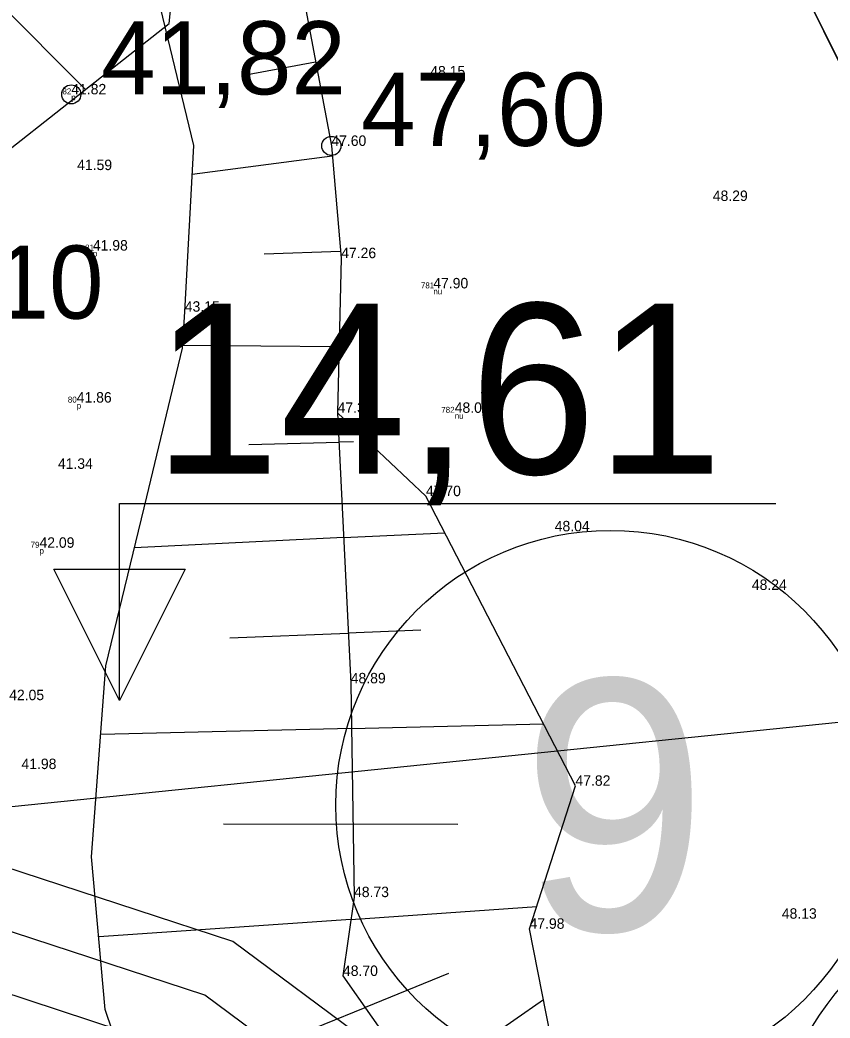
# Model space of a CAD drawing. Extents: x 700746 to 706058, y 6570320 to 6580460.
# Drawn here: x 703085.54 to 703112.68, y 6577214.62 to 6577248.05 of the extents above; entities that cross this region are included whole.
import ezdxf

# ---------------------------------------------------------------- set-up
doc = ezdxf.new("R2010")
doc.units = 0
for name, color, linetype in [('illumineerimisjooned', 7, 'Continuous'), ('jääkpaksus', 7, 'Continuous'), ('Kaevandatud ala', 7, 'Continuous'), ('kataster', 7, 'Continuous'), ('KORGUS-EH2000', 7, 'Continuous'), ('Lõige', 7, 'Continuous'), ('MOOTKOOD', 7, 'Continuous'), ('MOOTKORG-EH2000', 7, 'Continuous'), ('MOOTNR', 7, 'Continuous'), ('PIIR', 7, 'Continuous'), ('Plokid', 7, 'Continuous'), ('RELJEEF', 7, 'Continuous'), ('vahekiht', 7, 'Continuous'), ('VEEKOGU', 7, 'Continuous')]:
    doc.layers.add(name, color=color, linetype=linetype)

msp = doc.modelspace()

# ---------------------------------------------------------------- linework, layer by layer
at = {"layer": 'illumineerimisjooned'}
for points in [[(702862.311, 6577373.596), (702850.89, 6577377.293), (702839.79, 6577379.563), (702831.646, 6577378.473), (702820.821, 6577374.823), (702754.92, 6577346.017), (702742.145, 6577342.939), (702732.615, 6577342.189), (702714.765, 6577344.588), (702715.658, 6577336.409), (703090.802, 6577213.589), (703232.719, 6577108.158), (703252.344, 6577093.719)], [(703167.053, 6577159.433), (703091.733, 6577215.389), (702863.784, 6577290.018)]]:
    msp.add_lwpolyline(points, dxfattribs=at)
at = {"layer": 'jääkpaksus'}
msp.add_lwpolyline([(703088.869, 6577225.258), (703088.869, 6577231.858), (703110.869, 6577231.858)], dxfattribs=at)
msp.add_lwpolyline([(703088.869, 6577225.258), (703086.669, 6577229.658), (703091.069, 6577229.658)], close=True, dxfattribs=at)
at = {"layer": 'Kaevandatud ala'}
msp.add_line((702970.035, 6577363.415), (703087.727, 6577245.723), dxfattribs=at)
msp.add_lwpolyline([(703020.132, 6577213.175), (703028.583, 6577215.712), (703035.429, 6577216.388), (703043.119, 6577223.576), (703046.922, 6577230.341), (703054.529, 6577231.018), (703061.374, 6577228.396), (703067.29, 6577232.033), (703074.812, 6577238.628), (703081.403, 6577240.743), (703090.531, 6577247.93), (703091.499, 6577257.213)], dxfattribs=at)
at = {"layer": 'kataster'}
msp.add_lwpolyline([(702859.8, 6577465.72), (703125.43, 6577441.71), (703167.04, 6577172.32), (703141.54, 6577201.64), (703129.16, 6577218.59), (703119.31, 6577233.95), (703096.08, 6577280.59), (703057.1, 6577329.85), (703041.25, 6577339.7), (703019.19, 6577342.06), (703005.04, 6577344.66), (702961.68, 6577364.05), (702944.77, 6577367.92), (702900.72, 6577367.74), (702878.06, 6577370.59), (702863.2, 6577375.41), (702862.38, 6577440.12)], close=True, dxfattribs=at)
msp.add_lwpolyline([(702754.28, 6577347.92), (702820.1, 6577376.69), (702831.19, 6577380.43), (702839.86, 6577381.59), (702851.4, 6577379.23), (702863.2, 6577375.41), (702878.06, 6577370.59), (702900.72, 6577367.74), (702944.77, 6577367.92), (702961.68, 6577364.05), (703005.04, 6577344.66), (703019.19, 6577342.06), (703041.25, 6577339.7), (703057.1, 6577329.85), (703096.08, 6577280.59), (703119.31, 6577233.95), (703129.16, 6577218.59), (703141.54, 6577201.64), (703167.04, 6577172.32), (703168.73, 6577170.37), (703277.36, 6577072.83), (703231.53, 6577106.55), (703089.87, 6577211.79), (702713.81, 6577334.91)], dxfattribs=at)
at = {"layer": 'KORGUS-EH2000'}
for centre in [(703087.256, 6577245.556), (703095.97, 6577243.83)]:
    msp.add_circle(centre, 0.32, dxfattribs=at)
at = {"layer": 'Lõige'}
msp.add_lwpolyline([(702840.34, 6577295.661), (702901.645, 6577283.339), (702991.177, 6577252.569), (703074.081, 6577220.567), (703131.906, 6577226.463), (703178.085, 6577224.803)], dxfattribs=at)
at = {"layer": 'PIIR'}
for centre in [(703105.32, 6577221.752), (703119.956, 6577209.575)]:
    msp.add_circle(centre, 9.2, dxfattribs=at)
at = {"layer": 'Plokid'}
msp.add_lwpolyline([(703043.339, 6577445.098), (703121.898, 6577438.001), (703148.899, 6577263.565), (703163.227, 6577170.805), (703163.267, 6577170.746), (703164.325, 6577163.951), (703092.665, 6577217.188), (702865.809, 6577291.46), (702867.214, 6577375.329), (702866.384, 6577440.28), (702866.378, 6577440.34), (702866.377, 6577440.346), (702864.268, 6577461.276), (703043.339, 6577445.098)], dxfattribs=at)
at = {"layer": 'RELJEEF'}
for p, q in [((703093.164, 6577246.226), (703095.444, 6577246.64)), ((703096, 6577243.49), (703091.308, 6577242.872)), ((703093.717, 6577240.21), (703096.28, 6577240.303)), ((703096.231, 6577237.104), (703090.988, 6577237.147)), ((703093.209, 6577233.834), (703096.228, 6577233.906)), ((703096.714, 6577233.918), (703096.228, 6577233.906)), ((703096.383, 6577230.71), (703099.773, 6577230.874)), ((703096.383, 6577230.71), (703089.372, 6577230.369)), ((703092.572, 6577227.352), (703096.538, 6577227.514)), ((703098.972, 6577227.613), (703096.538, 6577227.514)), ((703096.643, 6577224.316), (703088.245, 6577224.113)), ((703096.643, 6577224.316), (703103.08, 6577224.471)), ((703092.356, 6577221.128), (703096.692, 6577221.116)), ((703100.212, 6577221.106), (703096.692, 6577221.116)), ((703096.625, 6577217.924), (703102.85, 6577218.355)), ((703096.625, 6577217.924), (703088.174, 6577217.338)), ((703099.891, 6577216.108), (703097.099, 6577214.976)), ((703098.937, 6577212.356), (703103.074, 6577215.247)), ((703093.261, 6577213.418), (703097.099, 6577214.976))]:
    msp.add_line(p, q, dxfattribs=at)
for points in [[(703092.61, 6577254.33), (703094.64, 6577250.94), (703095.97, 6577243.83), (703096.3, 6577240.07), (703096.18, 6577234.89), (703096.62, 6577225.83), (703096.73, 6577218.67), (703096.36, 6577216.03), (703099.27, 6577211.88), (703102.33, 6577207.48), (703108.69, 6577203.21), (703117.07, 6577197.4), (703119.26, 6577195.79), (703122.66, 6577191.02), (703124.13, 6577187.15), (703124.86, 6577183.98), (703126.36, 6577179.97), (703126.31, 6577178.16), (703125.42, 6577175.86), (703122.58, 6577172.87), (703122.53, 6577170.35), (703118.29, 6577167.65), (703112.56, 6577164.26)], [(703094.64, 6577250.94), (703095.97, 6577243.83), (703096.3, 6577240.07), (703096.18, 6577234.89), (703096.62, 6577225.83), (703096.73, 6577218.67), (703096.36, 6577216.03), (703099.27, 6577211.88)], [(703126.58, 6577194.82), (703126.07, 6577196.68), (703123.17, 6577199.85), (703119.24, 6577202.77), (703113.38, 6577206.06), (703109.84, 6577209.12), (703105.94, 6577210.1), (703103.88, 6577211.14), (703102.61, 6577217.61), (703104.15, 6577222.4), (703099.14, 6577232.1), (703096.18, 6577234.89)]]:
    msp.add_lwpolyline(points, dxfattribs=at)
at = {"layer": 'vahekiht'}
msp.add_open_spline([(702979.832, 6577405.847), (702968.107, 6577383.619), (702956.937, 6577340.299), (703007.686, 6577297.989), (703005.438, 6577248.778), (703018.696, 6577224.523), (703025.875, 6577210.26), (703039.06, 6577207.602), (703055.215, 6577200.514), (703065.918, 6577180.529), (703097.43, 6577186.962), (703125.436, 6577225.369), (703148.077, 6577281.443), (703138.931, 6577341.457), (703139.445, 6577382.673), (703130.544, 6577416.204), (703100.319, 6577426.617), (703061.125, 6577412.698), (703017.391, 6577461.228), (702989.678, 6577424.511), (702979.832, 6577405.847)], degree=3, dxfattribs=at)
msp.add_open_spline([(702979.832, 6577405.847), (702968.107, 6577383.619), (702956.937, 6577340.299), (703007.686, 6577297.989), (703005.438, 6577248.778), (703018.696, 6577224.523), (703025.875, 6577210.26), (703039.06, 6577207.602), (703055.215, 6577200.514), (703065.918, 6577180.529), (703097.43, 6577186.962), (703125.436, 6577225.369), (703148.077, 6577281.443), (703138.931, 6577341.457), (703139.445, 6577382.673), (703130.544, 6577416.204), (703100.319, 6577426.617), (703061.125, 6577412.698), (703017.391, 6577461.228), (702989.678, 6577424.511), (702979.832, 6577405.847)], degree=3, dxfattribs=at)
at = {"layer": 'VEEKOGU'}
msp.add_lwpolyline([(703120.39, 6577146.08), (703115.365, 6577147.77), (703110.383, 6577151.071), (703104.69, 6577159.71), (703106.266, 6577165.481), (703105.388, 6577174.722), (703104.887, 6577179.996), (703103.186, 6577185.693), (703099.755, 6577192.609), (703093.54, 6577202.31), (703089.925, 6577210.383), (703088.39, 6577214.903), (703087.936, 6577220.02), (703088.419, 6577226.416), (703089.783, 6577232.073), (703090.983, 6577237.053), (703091.059, 6577238.277), (703091.362, 6577243.838), (703090.24, 6577248.46), (703088.7, 6577253.3)], dxfattribs=at)
msp.add_lwpolyline([(703120.39, 6577146.08), (703115.365, 6577147.77), (703110.383, 6577151.071), (703104.69, 6577159.71), (703106.266, 6577165.481), (703105.388, 6577174.722), (703104.887, 6577179.996), (703103.186, 6577185.693), (703099.755, 6577192.609), (703093.54, 6577202.31), (703089.925, 6577210.383), (703088.39, 6577214.903), (703087.936, 6577220.02), (703088.419, 6577226.416), (703089.783, 6577232.073), (703090.983, 6577237.053), (703091.059, 6577238.277), (703091.362, 6577243.838), (703090.24, 6577248.46), (703088.7, 6577253.3)], dxfattribs=at)

# ---------------------------------------------------------------- texts
at = {"layer": 'jääkpaksus'}
msp.add_text('14,61', height=5.7, rotation=360, dxfattribs=at).set_placement((703090.007, 6577232.847))
at = {"layer": 'KORGUS-EH2000'}
for s, p in [('41,82', (703088.256, 6577245.556)), ('47,60', (703096.97, 6577243.83)), ('38,10', (703080.136, 6577238.043))]:
    msp.add_text(s, height=2.45, dxfattribs=at).set_placement(p)
at = {"layer": 'MOOTKOOD'}
for s, p in [('p', (703087.256, 6577245.356)), ('p', (703087.979, 6577240.125)), ('nu', (703099.386, 6577238.858)), ('p', (703087.439, 6577235.033)), ('nu', (703100.104, 6577234.69)), ('p', (703086.191, 6577230.171))]:
    msp.add_text(s, height=0.2, dxfattribs=at).set_placement(p)
at = {"layer": 'MOOTKORG-EH2000'}
for s, p in [('48.15', (703099.284, 6577246.156)), ('41.82', (703087.256, 6577245.556)), ('47.60', (703095.97, 6577243.83)), ('41.59', (703087.453, 6577243.02)), ('48.29', (703108.752, 6577241.985)), ('41.98', (703087.979, 6577240.325)), ('47.26', (703096.3, 6577240.07)), ('47.90', (703099.386, 6577239.058)), ('43.15', (703091.059, 6577238.277)), ('41.86', (703087.439, 6577235.233)), ('47.30', (703096.18, 6577234.89)), ('48.01', (703100.104, 6577234.89)), ('41.34', (703086.808, 6577233.014)), ('47.70', (703099.14, 6577232.1)), ('48.04', (703103.455, 6577230.921)), ('42.09', (703086.191, 6577230.371)), ('48.24', (703110.06, 6577228.959)), ('48.89', (703096.62, 6577225.83)), ('42.05', (703085.175, 6577225.266)), ('41.98', (703085.587, 6577222.959)), ('47.82', (703104.15, 6577222.4)), ('48.73', (703096.73, 6577218.67)), ('48.13', (703111.064, 6577217.947)), ('47.98', (703102.61, 6577217.61)), ('48.70', (703096.36, 6577216.03))]:
    msp.add_text(s, height=0.35, dxfattribs=at).set_placement(p)
at = {"layer": 'MOOTNR'}
for s, p in [('82', (703086.96, 6577245.556)), ('81', (703087.72, 6577240.325)), ('781', (703098.971, 6577239.058)), ('80', (703087.142, 6577235.233)), ('782', (703099.653, 6577234.89)), ('79', (703085.893, 6577230.371))]:
    msp.add_text(s, height=0.2, dxfattribs=at).set_placement(p)
at = {"layer": 'PIIR'}
msp.add_text('9', height=8.4, dxfattribs=at).set_placement((703102.33, 6577217.552))

doc.saveas('drawing.dxf')
